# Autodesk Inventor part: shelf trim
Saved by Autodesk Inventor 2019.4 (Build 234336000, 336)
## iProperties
Created: 2020-09
Part Number: shelf trim
Material: Generic
Document SubType Name: Modeling
Designer: Administrator
Density: 1 g/cm^3
Appearance: Default
Title: shelf trim
Author: Administrator
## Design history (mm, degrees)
feature "Body1"
body "Solid1"
